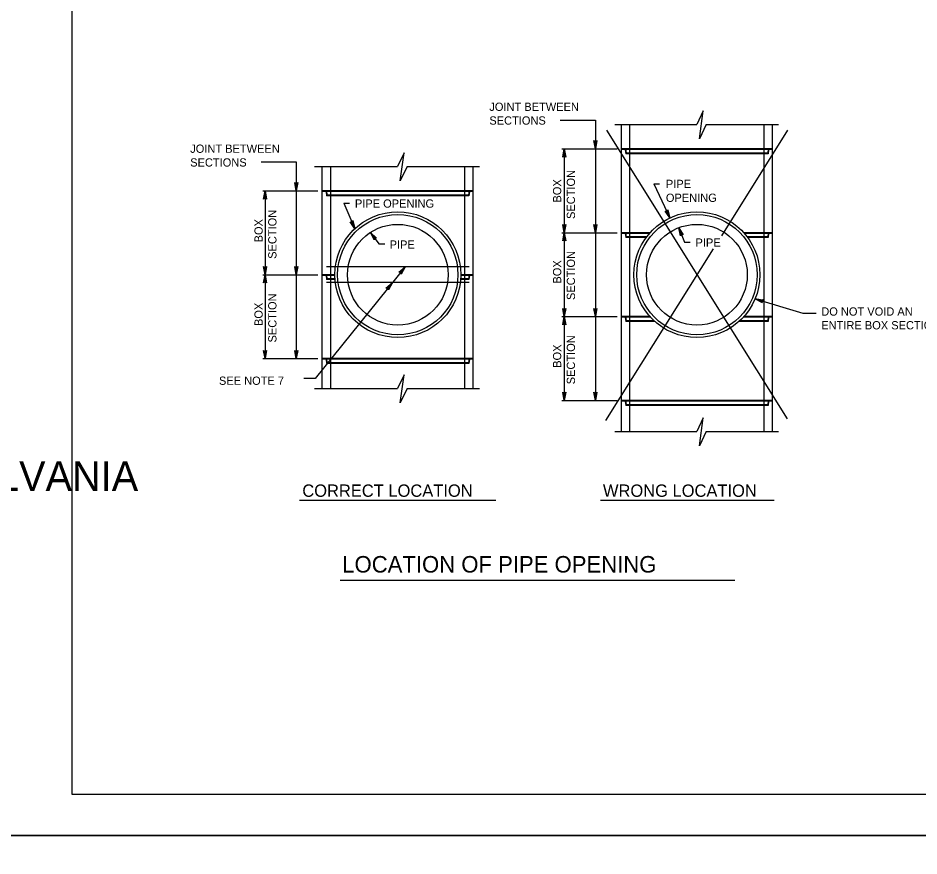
# Model space of a CAD drawing. Extents: x -6420 to 49575, y -4552 to 11624.
# Drawn here: x -838 to 236, y 1855 to 2854 of the extents above; entities that cross this region are included whole.
import ezdxf

# ---------------------------------------------------------------- set-up
doc = ezdxf.new("R2010")
doc.units = 0
doc.layers.add('1', color=7, linetype='Continuous')
doc.layers.add('PLT-BNDY', color=7, linetype='Continuous')

msp = doc.modelspace()

# ---------------------------------------------------------------- linework, layer by layer
at = {"layer": '1'}
for p, q in [((-191.8, 2732.6), (-149.9, 2732.6)), ((-149.9, 2732.6), (-149.9, 2398.2)), ((-136.7, 2720.4), (78.6, 2376.5)), ((-126.9, 2727.1), (-29.2, 2727.1)), ((-118.9, 2361.1), (-118.9, 2727.1)), ((-108.9, 2361.1), (-108.9, 2727.1)), ((-17.7, 2727.1), (68.5, 2727.1)), ((78.9, 2720.4), (0.2, 2594.7)), ((51.1, 2361.1), (51.1, 2727.1)), ((61.1, 2361.1), (61.1, 2727.1)), ((-189.8, 2698.2), (-123.9, 2698.2)), ((-187.1, 2698.2), (-187.1, 2598.2)), ((61.1, 2698.2), (-118.9, 2698.2)), ((61.1, 2697.4), (-118.9, 2697.4)), ((-114.3, 2697.4), (-113.7, 2692.4)), ((-113.9, 2698.2), (-113.3, 2693.2)), ((56.1, 2698.2), (55.5, 2693.2)), ((56.5, 2697.4), (55.9, 2692.4)), ((55.9, 2692.4), (-113.7, 2692.4)), ((55.5, 2693.2), (-113.3, 2693.2)), ((-548.3, 2682.6), (-506.4, 2682.6)), ((-506.4, 2682.6), (-506.4, 2448.2)), ((-484.8, 2677.1), (-385.8, 2677.1)), ((-475.4, 2412.4), (-475.4, 2677.1)), ((-465.4, 2412.4), (-465.4, 2677.1)), ((-374.2, 2677.1), (-287.9, 2677.1)), ((-305.4, 2412.4), (-305.4, 2677.1)), ((-295.4, 2412.4), (-295.4, 2677.1)), ((-80.3, 2656.5), (-73.5, 2656.5)), ((-80.3, 2656.5), (-61.1, 2615.9)), ((-546.3, 2648.2), (-480.5, 2648.2)), ((-543.6, 2648.2), (-543.6, 2548.2)), ((-295.4, 2648.2), (-475.4, 2648.2)), ((-295.4, 2647.4), (-475.4, 2647.4)), ((-470.8, 2647.4), (-470.2, 2642.4)), ((-470.4, 2648.2), (-469.8, 2643.2)), ((-300.6, 2642.4), (-470.2, 2642.4)), ((-301, 2643.2), (-469.8, 2643.2)), ((-300.4, 2648.2), (-301, 2643.2)), ((-300, 2647.4), (-300.6, 2642.4)), ((-449.8, 2633.4), (-442.9, 2633.4)), ((-449.8, 2633.4), (-436.6, 2603)), ((-417.8, 2598.7), (-407.8, 2584.9)), ((-50.4, 2604.2), (-43.8, 2586.9)), ((-189.8, 2598.2), (-123.9, 2598.2)), ((-187.1, 2598.2), (-187.1, 2498.2)), ((-84.8, 2598.2), (-118.9, 2598.2)), ((-85.5, 2597.4), (-118.9, 2597.4)), ((-114.3, 2597.4), (-113.7, 2592.4)), ((-113.9, 2598.2), (-113.3, 2593.2)), ((-89.5, 2592.4), (-113.7, 2592.4)), ((-88.9, 2593.2), (-113.3, 2593.2)), ((61.1, 2598.2), (27, 2598.2)), ((61.1, 2597.4), (27.7, 2597.4)), ((55.5, 2593.2), (31.1, 2593.2)), ((55.9, 2592.4), (31.7, 2592.4)), ((56.1, 2598.2), (55.5, 2593.2)), ((56.5, 2597.4), (55.9, 2592.4)), ((-407.8, 2584.9), (-400.9, 2584.9)), ((-9.6, 2579), (-137.9, 2374.2)), ((-43.8, 2586.9), (-36.9, 2586.9)), ((-300.5, 2557.6), (-470.3, 2557.6)), ((-546.3, 2548.2), (-480.5, 2548.2)), ((-543.6, 2548.2), (-543.6, 2448.2)), ((-460.4, 2548.2), (-475.4, 2548.2)), ((-460.4, 2547.4), (-475.4, 2547.4)), ((-470.8, 2547.4), (-470.2, 2542.4)), ((-470.4, 2548.2), (-469.8, 2543.2)), ((-295.4, 2548.2), (-310.4, 2548.2)), ((-295.4, 2547.4), (-310.4, 2547.4)), ((-300.4, 2548.2), (-301, 2543.2)), ((-300, 2547.4), (-300.6, 2542.4)), ((-300.5, 2538.7), (-470.3, 2538.7)), ((-460.2, 2542.4), (-470.2, 2542.4)), ((-460.3, 2543.2), (-469.8, 2543.2)), ((-300.6, 2542.4), (-310.7, 2542.4)), ((-301, 2543.2), (-310.6, 2543.2)), ((-189.8, 2498.2), (-123.9, 2498.2)), ((-187.1, 2498.2), (-187.1, 2398.2)), ((-84.8, 2498.2), (-118.9, 2498.2)), ((-84, 2497.4), (-118.9, 2497.4)), ((-114.3, 2497.4), (-113.7, 2492.4)), ((-113.9, 2498.2), (-113.3, 2493.2)), ((-79, 2492.4), (-113.7, 2492.4)), ((-79.9, 2493.2), (-113.3, 2493.2)), ((55.9, 2492.4), (21.2, 2492.4)), ((55.5, 2493.2), (22.1, 2493.2)), ((61.1, 2497.4), (26.2, 2497.4)), ((61.1, 2498.2), (27, 2498.2)), ((56.1, 2498.2), (55.5, 2493.2)), ((56.5, 2497.4), (55.9, 2492.4)), ((-546.3, 2448.2), (-480.5, 2448.2)), ((-295.4, 2448.2), (-475.4, 2448.2)), ((-295.4, 2447.4), (-475.4, 2447.4)), ((-470.8, 2447.4), (-470.2, 2442.4)), ((-470.4, 2448.2), (-469.8, 2443.2)), ((-300.6, 2442.4), (-470.2, 2442.4)), ((-301, 2443.2), (-469.8, 2443.2)), ((-300.4, 2448.2), (-301, 2443.2)), ((-300, 2447.4), (-300.6, 2442.4)), ((-484.8, 2412.4), (-385.8, 2412.4)), ((-374.2, 2412.4), (-287.9, 2412.4)), ((-189.8, 2398.2), (-123.9, 2398.2)), ((61.1, 2398.2), (-118.9, 2398.2)), ((61.1, 2397.4), (-118.9, 2397.4)), ((-114.3, 2397.4), (-113.7, 2392.4)), ((-113.9, 2398.2), (-113.3, 2393.2)), ((56.1, 2398.2), (55.5, 2393.2)), ((56.5, 2397.4), (55.9, 2392.4)), ((55.9, 2392.4), (-113.7, 2392.4)), ((55.5, 2393.2), (-113.3, 2393.2)), ((-126.9, 2361.1), (-29.2, 2361.1)), ((-17.7, 2361.1), (68.5, 2361.1)), ((-502.5, 2279.2), (-268.5, 2279.2)), ((-143.8, 2279.2), (63.2, 2279.2)), ((-454.1, 2184.1), (16.3, 2184.1))]:
    msp.add_line(p, q, dxfattribs=at)
for points in [[(1804.7, 1929), (1804.7, 3779.4), (-774, 3779.4), (-774, 1929), (1804.7, 1929), (1804.7, 2015.5), (1148.5, 2015.5), (1148.5, 2227.7), (1804.7, 2227.7), (1804.7, 2322.7), (1148.5, 2322.7), (1148.5, 1929), (1407.1, 1929), (1407.1, 2015.5), (1407.1, 1929), (1659.7, 1929), (1659.7, 2015.5), (1659.7, 1975.1), (1804.7, 1975.1)], [(-17.7, 2727.1), (-26, 2710.1), (-21.5, 2743.4), (-29.2, 2727.1)], [(-149.9, 2698.2), (-151.7, 2708), (-151.4, 2707.6), (-151.2, 2707.2), (-150.8, 2707), (-150.5, 2706.8), (-150.2, 2706.8), (-149.9, 2706.7), (-149.5, 2706.8), (-149.2, 2706.8), (-148.9, 2707), (-148.5, 2707.2), (-148.3, 2707.6), (-148, 2708), (-149.9, 2698.2), (-148.3, 2707.6), (-148.5, 2707.2), (-149.9, 2698.2), (-148.9, 2707), (-149.2, 2706.8), (-149.9, 2698.2), (-149.5, 2706.8), (-149.9, 2706.7), (-149.9, 2698.2), (-150.2, 2706.8), (-150.5, 2706.8), (-149.9, 2698.2), (-150.8, 2707), (-151.2, 2707.2), (-149.9, 2698.2), (-151.4, 2707.6)], [(-187.1, 2698.2), (-185.3, 2688.4), (-185.5, 2688.8), (-185.8, 2689.2), (-186.1, 2689.4), (-186.4, 2689.5), (-186.8, 2689.6), (-187.1, 2689.7), (-187.4, 2689.6), (-187.8, 2689.5), (-188.1, 2689.4), (-188.4, 2689.2), (-188.7, 2688.8), (-188.9, 2688.4), (-187.1, 2698.2), (-188.7, 2688.8), (-188.4, 2689.2), (-187.1, 2698.2), (-188.1, 2689.4), (-187.8, 2689.5), (-187.1, 2698.2), (-187.4, 2689.6), (-187.1, 2689.7), (-187.1, 2698.2), (-186.8, 2689.6), (-186.4, 2689.5), (-187.1, 2698.2), (-186.1, 2689.4), (-185.8, 2689.2), (-187.1, 2698.2), (-185.5, 2688.8)], [(-374.2, 2677.1), (-382.6, 2660.1), (-378, 2693.4), (-385.8, 2677.1)], [(-506.4, 2648.2), (-508.2, 2658), (-508, 2657.6), (-507.7, 2657.2), (-507.4, 2657), (-507, 2656.8), (-506.7, 2656.8), (-506.4, 2656.7), (-506.1, 2656.8), (-505.7, 2656.8), (-505.4, 2657), (-505.1, 2657.2), (-504.8, 2657.6), (-504.6, 2658), (-506.4, 2648.2), (-504.8, 2657.6), (-505.1, 2657.2), (-506.4, 2648.2), (-505.4, 2657), (-505.7, 2656.8), (-506.4, 2648.2), (-506.1, 2656.8), (-506.4, 2656.7), (-506.4, 2648.2), (-506.7, 2656.8), (-507, 2656.8), (-506.4, 2648.2), (-507.4, 2657), (-507.7, 2657.2), (-506.4, 2648.2), (-508, 2657.6)], [(-543.6, 2648.2), (-541.8, 2638.4), (-542.1, 2638.8), (-542.3, 2639.2), (-542.6, 2639.4), (-543, 2639.5), (-543.3, 2639.6), (-543.6, 2639.7), (-544, 2639.6), (-544.3, 2639.5), (-544.6, 2639.4), (-544.9, 2639.2), (-545.2, 2638.8), (-545.5, 2638.4), (-543.6, 2648.2), (-545.2, 2638.8), (-544.9, 2639.2), (-543.6, 2648.2), (-544.6, 2639.4), (-544.3, 2639.5), (-543.6, 2648.2), (-544, 2639.6), (-543.6, 2639.7), (-543.6, 2648.2), (-543.3, 2639.6), (-543, 2639.5), (-543.6, 2648.2), (-542.6, 2639.4), (-542.3, 2639.2), (-543.6, 2648.2), (-542.1, 2638.8)], [(-61.1, 2615.9), (-66.9, 2624), (-66.5, 2623.8), (-66.1, 2623.5), (-65.7, 2623.5), (-65.4, 2623.5), (-65, 2623.6), (-64.7, 2623.6), (-64.4, 2623.8), (-64.2, 2624), (-64, 2624.3), (-63.7, 2624.7), (-63.7, 2625.1), (-63.6, 2625.6), (-61.1, 2615.9), (-63.7, 2625.1), (-63.7, 2624.7), (-61.1, 2615.9), (-64, 2624.3), (-64.2, 2624), (-61.1, 2615.9), (-64.4, 2623.8), (-64.7, 2623.6), (-61.1, 2615.9), (-65, 2623.6), (-65.4, 2623.5), (-61.1, 2615.9), (-65.7, 2623.5), (-66.1, 2623.5), (-61.1, 2615.9), (-66.5, 2623.8)], [(-436.6, 2603), (-442.2, 2611.3), (-441.8, 2611), (-441.4, 2610.8), (-441, 2610.7), (-440.6, 2610.7), (-440.3, 2610.8), (-440, 2610.9), (-439.7, 2611), (-439.4, 2611.2), (-439.2, 2611.5), (-439, 2611.8), (-438.9, 2612.3), (-438.8, 2612.7), (-436.6, 2603), (-438.9, 2612.3), (-439, 2611.8), (-436.6, 2603), (-439.2, 2611.5), (-439.4, 2611.2), (-436.6, 2603), (-439.7, 2611), (-440, 2610.9), (-436.6, 2603), (-440.3, 2610.8), (-440.6, 2610.7), (-436.6, 2603), (-441, 2610.7), (-441.4, 2610.8), (-436.6, 2603), (-441.8, 2611)], [(-417.8, 2598.7), (-410.6, 2591.8), (-411, 2592), (-411.5, 2592.2), (-411.8, 2592.1), (-412.2, 2592.1), (-412.5, 2591.9), (-412.8, 2591.8), (-413, 2591.5), (-413.3, 2591.3), (-413.4, 2591), (-413.6, 2590.6), (-413.6, 2590.1), (-413.6, 2589.7), (-417.8, 2598.7), (-413.6, 2590.1), (-413.6, 2590.6), (-417.8, 2598.7), (-413.4, 2591), (-413.3, 2591.3), (-417.8, 2598.7), (-413, 2591.5), (-412.8, 2591.8), (-417.8, 2598.7), (-412.5, 2591.9), (-412.2, 2592.1), (-417.8, 2598.7), (-411.8, 2592.1), (-411.5, 2592.2), (-417.8, 2598.7), (-411, 2592)], [(-187.1, 2598.2), (-188.9, 2608), (-188.7, 2607.6), (-188.4, 2607.2), (-188.1, 2607), (-187.8, 2606.8), (-187.4, 2606.8), (-187.1, 2606.7), (-186.8, 2606.8), (-186.4, 2606.8), (-186.1, 2607), (-185.8, 2607.2), (-185.5, 2607.6), (-185.3, 2608), (-187.1, 2598.2), (-185.5, 2607.6), (-185.8, 2607.2), (-187.1, 2598.2), (-186.1, 2607), (-186.4, 2606.8), (-187.1, 2598.2), (-186.8, 2606.8), (-187.1, 2606.7), (-187.1, 2598.2), (-187.4, 2606.8), (-187.8, 2606.8), (-187.1, 2598.2), (-188.1, 2607), (-188.4, 2607.2), (-187.1, 2598.2), (-188.7, 2607.6)], [(-149.9, 2598.2), (-151.7, 2608), (-151.4, 2607.6), (-151.2, 2607.2), (-150.8, 2607), (-150.5, 2606.8), (-150.2, 2606.8), (-149.9, 2606.7), (-149.5, 2606.8), (-149.2, 2606.8), (-148.9, 2607), (-148.5, 2607.2), (-148.3, 2607.6), (-148, 2608), (-149.9, 2598.2), (-148.3, 2607.6), (-148.5, 2607.2), (-149.9, 2598.2), (-148.9, 2607), (-149.2, 2606.8), (-149.9, 2598.2), (-149.5, 2606.8), (-149.9, 2606.7), (-149.9, 2598.2), (-150.2, 2606.8), (-150.5, 2606.8), (-149.9, 2598.2), (-150.8, 2607), (-151.2, 2607.2), (-149.9, 2598.2), (-151.4, 2607.6)], [(-50.4, 2604.2), (-45.2, 2595.7), (-45.6, 2596), (-46, 2596.2), (-46.3, 2596.3), (-46.7, 2596.4), (-47, 2596.3), (-47.4, 2596.2), (-47.7, 2596.1), (-47.9, 2595.9), (-48.2, 2595.6), (-48.4, 2595.3), (-48.5, 2594.8), (-48.6, 2594.4), (-50.4, 2604.2), (-48.5, 2594.8), (-48.4, 2595.3), (-50.4, 2604.2), (-48.2, 2595.6), (-47.9, 2595.9), (-50.4, 2604.2), (-47.7, 2596.1), (-47.4, 2596.2), (-50.4, 2604.2), (-47, 2596.3), (-46.7, 2596.4), (-50.4, 2604.2), (-46.3, 2596.3), (-46, 2596.2), (-50.4, 2604.2), (-45.6, 2596)], [(-187.1, 2598.2), (-185.3, 2588.4), (-185.5, 2588.8), (-185.8, 2589.2), (-186.1, 2589.4), (-186.4, 2589.5), (-186.8, 2589.6), (-187.1, 2589.7), (-187.4, 2589.6), (-187.8, 2589.5), (-188.1, 2589.4), (-188.4, 2589.2), (-188.7, 2588.8), (-188.9, 2588.4), (-187.1, 2598.2), (-188.7, 2588.8), (-188.4, 2589.2), (-187.1, 2598.2), (-188.1, 2589.4), (-187.8, 2589.5), (-187.1, 2598.2), (-187.4, 2589.6), (-187.1, 2589.7), (-187.1, 2598.2), (-186.8, 2589.6), (-186.4, 2589.5), (-187.1, 2598.2), (-186.1, 2589.4), (-185.8, 2589.2), (-187.1, 2598.2), (-185.5, 2588.8)], [(-543.6, 2548.2), (-545.5, 2558), (-545.2, 2557.6), (-544.9, 2557.2), (-544.6, 2557), (-544.3, 2556.8), (-544, 2556.8), (-543.6, 2556.7), (-543.3, 2556.8), (-543, 2556.8), (-542.6, 2557), (-542.3, 2557.2), (-542.1, 2557.6), (-541.8, 2558), (-543.6, 2548.2), (-542.1, 2557.6), (-542.3, 2557.2), (-543.6, 2548.2), (-542.6, 2557), (-543, 2556.8), (-543.6, 2548.2), (-543.3, 2556.8), (-543.6, 2556.7), (-543.6, 2548.2), (-544, 2556.8), (-544.3, 2556.8), (-543.6, 2548.2), (-544.6, 2557), (-544.9, 2557.2), (-543.6, 2548.2), (-545.2, 2557.6)], [(-506.4, 2548.2), (-508.2, 2558), (-508, 2557.6), (-507.7, 2557.2), (-507.4, 2557), (-507, 2556.8), (-506.7, 2556.8), (-506.4, 2556.7), (-506.1, 2556.8), (-505.7, 2556.8), (-505.4, 2557), (-505.1, 2557.2), (-504.8, 2557.6), (-504.6, 2558), (-506.4, 2548.2), (-504.8, 2557.6), (-505.1, 2557.2), (-506.4, 2548.2), (-505.4, 2557), (-505.7, 2556.8), (-506.4, 2548.2), (-506.1, 2556.8), (-506.4, 2556.7), (-506.4, 2548.2), (-506.7, 2556.8), (-507, 2556.8), (-506.4, 2548.2), (-507.4, 2557), (-507.7, 2557.2), (-506.4, 2548.2), (-508, 2557.6)], [(-376.7, 2557.6), (-484, 2424.6), (-497.5, 2424.6)], [(-376.7, 2557.6), (-381.3, 2548.9), (-381.3, 2549.4), (-381.3, 2549.8), (-381.4, 2550.2), (-381.5, 2550.5), (-381.8, 2550.8), (-382, 2551), (-382.3, 2551.2), (-382.5, 2551.4), (-382.9, 2551.4), (-383.3, 2551.5), (-383.7, 2551.3), (-384.2, 2551.2), (-376.7, 2557.6), (-383.7, 2551.3), (-383.3, 2551.5), (-376.7, 2557.6), (-382.9, 2551.4), (-382.5, 2551.4), (-376.7, 2557.6), (-382.3, 2551.2), (-382, 2551), (-376.7, 2557.6), (-381.8, 2550.8), (-381.5, 2550.5), (-376.7, 2557.6), (-381.4, 2550.2), (-381.3, 2549.8), (-376.7, 2557.6), (-381.3, 2549.4)], [(-543.6, 2548.2), (-541.8, 2538.4), (-542.1, 2538.8), (-542.3, 2539.2), (-542.6, 2539.4), (-543, 2539.5), (-543.3, 2539.6), (-543.6, 2539.7), (-544, 2539.6), (-544.3, 2539.5), (-544.6, 2539.4), (-544.9, 2539.2), (-545.2, 2538.8), (-545.5, 2538.4), (-543.6, 2548.2), (-545.2, 2538.8), (-544.9, 2539.2), (-543.6, 2548.2), (-544.6, 2539.4), (-544.3, 2539.5), (-543.6, 2548.2), (-544, 2539.6), (-543.6, 2539.7), (-543.6, 2548.2), (-543.3, 2539.6), (-543, 2539.5), (-543.6, 2548.2), (-542.6, 2539.4), (-542.3, 2539.2), (-543.6, 2548.2), (-542.1, 2538.8)], [(-391.9, 2538.7), (-396.6, 2530), (-396.6, 2530.4), (-396.5, 2530.9), (-396.7, 2531.3), (-396.8, 2531.6), (-397, 2531.9), (-397.3, 2532.1), (-397.5, 2532.3), (-397.8, 2532.4), (-398.2, 2532.5), (-398.6, 2532.5), (-399, 2532.4), (-399.5, 2532.3), (-391.9, 2538.7), (-399, 2532.4), (-398.6, 2532.5), (-391.9, 2538.7), (-398.2, 2532.5), (-397.8, 2532.4), (-391.9, 2538.7), (-397.5, 2532.3), (-397.3, 2532.1), (-391.9, 2538.7), (-397, 2531.9), (-396.8, 2531.6), (-391.9, 2538.7), (-396.7, 2531.3), (-396.5, 2530.9), (-391.9, 2538.7), (-396.6, 2530.4)], [(40.4, 2519.4), (97.3, 2502.2), (113.1, 2502.2)], [(40.4, 2519.4), (50.2, 2518.3), (49.7, 2518.2), (49.3, 2518), (49, 2517.8), (48.7, 2517.5), (48.6, 2517.2), (48.5, 2516.9), (48.4, 2516.6), (48.4, 2516.3), (48.5, 2515.9), (48.6, 2515.5), (48.8, 2515.2), (49.1, 2514.8), (40.4, 2519.4), (48.8, 2515.2), (48.6, 2515.5), (40.4, 2519.4), (48.5, 2515.9), (48.4, 2516.3), (40.4, 2519.4), (48.4, 2516.6), (48.5, 2516.9), (40.4, 2519.4), (48.6, 2517.2), (48.7, 2517.5), (40.4, 2519.4), (49, 2517.8), (49.3, 2518), (40.4, 2519.4), (49.7, 2518.2)], [(-187.1, 2498.2), (-188.9, 2508), (-188.7, 2507.6), (-188.4, 2507.2), (-188.1, 2507), (-187.8, 2506.8), (-187.4, 2506.8), (-187.1, 2506.7), (-186.8, 2506.8), (-186.4, 2506.8), (-186.1, 2507), (-185.8, 2507.2), (-185.5, 2507.6), (-185.3, 2508), (-187.1, 2498.2), (-185.5, 2507.6), (-185.8, 2507.2), (-187.1, 2498.2), (-186.1, 2507), (-186.4, 2506.8), (-187.1, 2498.2), (-186.8, 2506.8), (-187.1, 2506.7), (-187.1, 2498.2), (-187.4, 2506.8), (-187.8, 2506.8), (-187.1, 2498.2), (-188.1, 2507), (-188.4, 2507.2), (-187.1, 2498.2), (-188.7, 2507.6)], [(-149.9, 2498.2), (-151.7, 2508), (-151.4, 2507.6), (-151.2, 2507.2), (-150.8, 2507), (-150.5, 2506.8), (-150.2, 2506.8), (-149.9, 2506.7), (-149.5, 2506.8), (-149.2, 2506.8), (-148.9, 2507), (-148.5, 2507.2), (-148.3, 2507.6), (-148, 2508), (-149.9, 2498.2), (-148.3, 2507.6), (-148.5, 2507.2), (-149.9, 2498.2), (-148.9, 2507), (-149.2, 2506.8), (-149.9, 2498.2), (-149.5, 2506.8), (-149.9, 2506.7), (-149.9, 2498.2), (-150.2, 2506.8), (-150.5, 2506.8), (-149.9, 2498.2), (-150.8, 2507), (-151.2, 2507.2), (-149.9, 2498.2), (-151.4, 2507.6)], [(-187.1, 2498.2), (-185.3, 2488.4), (-185.5, 2488.8), (-185.8, 2489.2), (-186.1, 2489.4), (-186.4, 2489.5), (-186.8, 2489.6), (-187.1, 2489.7), (-187.4, 2489.6), (-187.8, 2489.5), (-188.1, 2489.4), (-188.4, 2489.2), (-188.7, 2488.8), (-188.9, 2488.4), (-187.1, 2498.2), (-188.7, 2488.8), (-188.4, 2489.2), (-187.1, 2498.2), (-188.1, 2489.4), (-187.8, 2489.5), (-187.1, 2498.2), (-187.4, 2489.6), (-187.1, 2489.7), (-187.1, 2498.2), (-186.8, 2489.6), (-186.4, 2489.5), (-187.1, 2498.2), (-186.1, 2489.4), (-185.8, 2489.2), (-187.1, 2498.2), (-185.5, 2488.8)], [(-543.6, 2448.2), (-545.5, 2458), (-545.2, 2457.6), (-544.9, 2457.2), (-544.6, 2457), (-544.3, 2456.8), (-544, 2456.8), (-543.6, 2456.7), (-543.3, 2456.8), (-543, 2456.8), (-542.6, 2457), (-542.3, 2457.2), (-542.1, 2457.6), (-541.8, 2458), (-543.6, 2448.2), (-542.1, 2457.6), (-542.3, 2457.2), (-543.6, 2448.2), (-542.6, 2457), (-543, 2456.8), (-543.6, 2448.2), (-543.3, 2456.8), (-543.6, 2456.7), (-543.6, 2448.2), (-544, 2456.8), (-544.3, 2456.8), (-543.6, 2448.2), (-544.6, 2457), (-544.9, 2457.2), (-543.6, 2448.2), (-545.2, 2457.6)], [(-506.4, 2448.2), (-508.2, 2458), (-508, 2457.6), (-507.7, 2457.2), (-507.4, 2457), (-507, 2456.8), (-506.7, 2456.8), (-506.4, 2456.7), (-506.1, 2456.8), (-505.7, 2456.8), (-505.4, 2457), (-505.1, 2457.2), (-504.8, 2457.6), (-504.6, 2458), (-506.4, 2448.2), (-504.8, 2457.6), (-505.1, 2457.2), (-506.4, 2448.2), (-505.4, 2457), (-505.7, 2456.8), (-506.4, 2448.2), (-506.1, 2456.8), (-506.4, 2456.7), (-506.4, 2448.2), (-506.7, 2456.8), (-507, 2456.8), (-506.4, 2448.2), (-507.4, 2457), (-507.7, 2457.2), (-506.4, 2448.2), (-508, 2457.6)], [(-374.2, 2412.4), (-382.6, 2395.4), (-378, 2428.7), (-385.8, 2412.4)], [(-187.1, 2398.2), (-188.9, 2408), (-188.7, 2407.6), (-188.4, 2407.2), (-188.1, 2407), (-187.8, 2406.8), (-187.4, 2406.8), (-187.1, 2406.7), (-186.8, 2406.8), (-186.4, 2406.8), (-186.1, 2407), (-185.8, 2407.2), (-185.5, 2407.6), (-185.3, 2408), (-187.1, 2398.2), (-185.5, 2407.6), (-185.8, 2407.2), (-187.1, 2398.2), (-186.1, 2407), (-186.4, 2406.8), (-187.1, 2398.2), (-186.8, 2406.8), (-187.1, 2406.7), (-187.1, 2398.2), (-187.4, 2406.8), (-187.8, 2406.8), (-187.1, 2398.2), (-188.1, 2407), (-188.4, 2407.2), (-187.1, 2398.2), (-188.7, 2407.6)], [(-149.9, 2398.2), (-151.7, 2408), (-151.4, 2407.6), (-151.2, 2407.2), (-150.8, 2407), (-150.5, 2406.8), (-150.2, 2406.8), (-149.9, 2406.7), (-149.5, 2406.8), (-149.2, 2406.8), (-148.9, 2407), (-148.5, 2407.2), (-148.3, 2407.6), (-148, 2408), (-149.9, 2398.2), (-148.3, 2407.6), (-148.5, 2407.2), (-149.9, 2398.2), (-148.9, 2407), (-149.2, 2406.8), (-149.9, 2398.2), (-149.5, 2406.8), (-149.9, 2406.7), (-149.9, 2398.2), (-150.2, 2406.8), (-150.5, 2406.8), (-149.9, 2398.2), (-150.8, 2407), (-151.2, 2407.2), (-149.9, 2398.2), (-151.4, 2407.6)], [(-17.7, 2361.1), (-26, 2344.1), (-21.5, 2377.4), (-29.2, 2361.1)]]:
    msp.add_lwpolyline(points, dxfattribs=at)
for centre, radius in [((-385.4, 2548.2), 75), ((-28.9, 2548.2), 75), ((-385.4, 2548.2), 71.7), ((-385.4, 2548.2), 71.7), ((-28.9, 2548.2), 71.7), ((-28.9, 2548.2), 71.7), ((-385.4, 2548.2), 60), ((-385.4, 2548.2), 60), ((-28.9, 2548.2), 60), ((-28.9, 2548.2), 60)]:
    msp.add_circle(centre, radius, dxfattribs=at)
at = {"layer": 'PLT-BNDY'}
for points in [[(-902, 3828.6), (1857.2, 3828.6), (1857.2, 1879.8), (-902, 1879.8)], [(-902, 1879.8), (1857.2, 1879.8), (1857.2, -69), (-902, -69)]]:
    msp.add_lwpolyline(points, close=True, dxfattribs=at)

# ---------------------------------------------------------------- texts
at = {"layer": '1'}
for s, height, p in [('JOINT BETWEEN', 9.843, (-276.3, 2743.5)), ('SECTIONS', 9.84, (-276.3, 2727.1)), ('JOINT BETWEEN', 9.843, (-632.8, 2693.5)), ('SECTIONS', 9.84, (-632.8, 2677.1)), ('PIPE', 9.84, (-65.9, 2651.5)), ('OPENING', 9.84, (-65.9, 2635)), ('PIPE OPENING', 9.843, (-436.5, 2628.1)), ('PIPE', 9.84, (-395.1, 2579.2)), ('PIPE', 9.84, (-30.6, 2581.6)), ('DO NOT VOID AN', 9.843, (119.3, 2499.4)), ('ENTIRE BOX SECTION', 9.843, (119.3, 2483)), ('SEE NOTE 7', 9.84, (-598.5, 2416.9)), ('COMMONWEALTH OF PENNSYLVANIA', 35.379, (-1567.5, 2290.4)), ('CORRECT LOCATION', 14.69, (-499.2, 2283.4)), ('WRONG LOCATION', 14.69, (-140.9, 2283.4)), ('LOCATION OF PIPE OPENING', 19.685, (-451.6, 2193.1))]:
    msp.add_text(s, height=height, dxfattribs=at).set_placement(p)
for s, p in [('SECTION', (-174.2, 2614.6)), ('BOX', (-190.6, 2634.2)), ('SECTION', (-530, 2567.1)), ('BOX', (-546.4, 2586.7)), ('SECTION', (-174.2, 2518)), ('BOX', (-190.6, 2537.6)), ('SECTION', (-530, 2467.4)), ('BOX', (-546.4, 2487)), ('SECTION', (-174.2, 2417.5)), ('BOX', (-190.6, 2437.2))]:
    msp.add_text(s, height=9.84, rotation=90, dxfattribs=at).set_placement(p)

doc.saveas('drawing.dxf')
